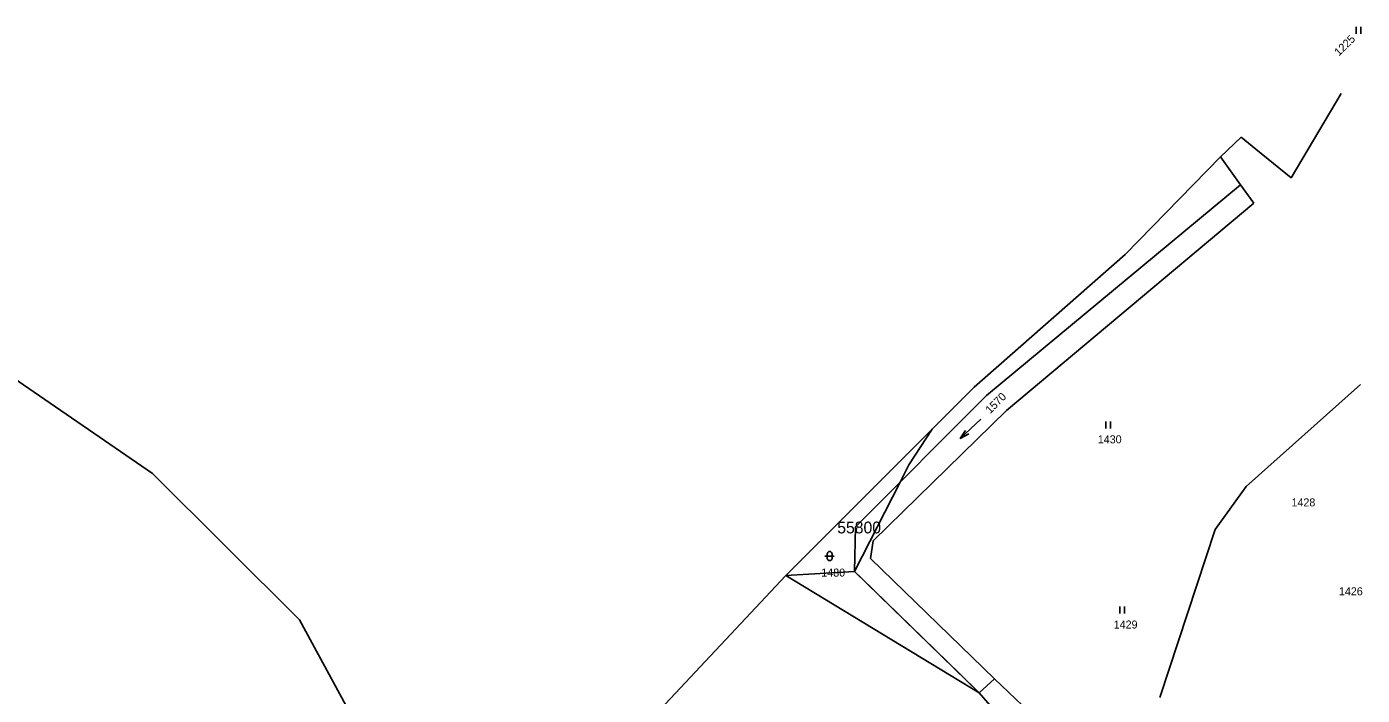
# Model space of a CAD drawing. Extents: x -792913 to -792113, y -1112764 to -1111548.
# Drawn here: x -792564 to -792280.2, y -1111690.4 to -1111548.5 of the extents above; entities that cross this region are included whole.
import ezdxf

# ---------------------------------------------------------------- set-up
doc = ezdxf.new("R2010")
doc.units = 0
for name, color, linetype in [('Vrstva 1', 7, 'Continuous'), ('Vrstva 11', 7, 'Continuous'), ('Vrstva 2', 7, 'Continuous'), ('Vrstva 3', 7, 'Continuous')]:
    doc.layers.add(name, color=color, linetype=linetype)

msp = doc.modelspace()

# ---------------------------------------------------------------- linework, layer by layer
at = {"layer": 'Vrstva 1'}
for p, q in [((-792284.7, -1111562.64), (-792295.38, -1111580.58)), ((-792306, -1111571.97), (-792310.36, -1111576.12)), ((-792306, -1111571.97), (-792306, -1111571.97)), ((-792302.87, -1111574.51), (-792306, -1111571.97)), ((-792330.62, -1111596.83), (-792310.36, -1111576.12)), ((-792310.36, -1111576.12), (-792306.1, -1111582.06)), ((-792302.87, -1111574.51), (-792302.87, -1111574.51)), ((-792295.38, -1111580.58), (-792302.87, -1111574.51)), ((-792306.1, -1111582.06), (-792360.09, -1111626.82)), ((-792306.1, -1111582.06), (-792303.31, -1111585.96)), ((-792295.38, -1111580.58), (-792295.38, -1111580.58)), ((-792303.31, -1111585.96), (-792355.85, -1111629.99)), ((-792303.31, -1111585.96), (-792303.31, -1111585.96)), ((-792362.73, -1111625), (-792330.62, -1111596.83)), ((-792537.29, -1111643.34), (-792573.5, -1111618.48)), ((-792402.71, -1111664.98), (-792362.73, -1111625)), ((-792304.88, -1111646.11), (-792280.6, -1111624.45)), ((-792360.09, -1111626.82), (-792387.93, -1111654.66)), ((-792355.85, -1111629.99), (-792384.15, -1111657.66)), ((-792506.06, -1111674.4), (-792537.29, -1111643.34)), ((-792311.52, -1111655.25), (-792304.88, -1111646.11)), ((-792387.93, -1111654.66), (-792388.1, -1111664.15)), ((-792323.22, -1111690.93), (-792311.52, -1111655.25)), ((-792384.15, -1111657.66), (-792384.7, -1111661.39)), ((-792384.7, -1111661.39), (-792358.41, -1111686.91)), ((-792402.71, -1111664.98), (-792456.34, -1111722.07)), ((-792361.64, -1111689.93), (-792402.71, -1111664.98)), ((-792388.1, -1111664.15), (-792361.64, -1111689.93)), ((-792485.77, -1111711.57), (-792506.06, -1111674.4)), ((-792358.41, -1111686.91), (-792361.64, -1111689.93)), ((-792358.41, -1111686.91), (-792358.41, -1111686.91)), ((-792358.41, -1111686.91), (-792339.22, -1111705.06)), ((-792344.27, -1111709.86), (-792361.64, -1111689.93))]:
    msp.add_line(p, q, dxfattribs=at)
at = {"layer": 'Vrstva 11'}
for p, q in [((-792310.36, -1111576.12), (-792306, -1111571.97)), ((-792330.62, -1111596.83), (-792310.36, -1111576.12)), ((-792362.73, -1111625), (-792330.62, -1111596.83)), ((-792371.64, -1111633.91), (-792362.73, -1111625)), ((-792402.71, -1111664.98), (-792371.64, -1111633.91)), ((-792371.64, -1111633.91), (-792376.56, -1111641.5)), ((-792376.56, -1111641.5), (-792378.42, -1111645.15)), ((-792378.42, -1111645.15), (-792388.1, -1111664.15)), ((-792402.71, -1111664.98), (-792388.1, -1111664.15)), ((-792388.1, -1111664.15), (-792386.54, -1111665.67)), ((-792386.54, -1111665.67), (-792365.76, -1111685.91)), ((-792365.76, -1111685.91), (-792361.64, -1111689.93)), ((-792361.64, -1111689.93), (-792344.27, -1111709.86))]:
    msp.add_line(p, q, dxfattribs=at)
at = {"layer": 'Vrstva 3'}
for p, q in [((-792281.52, -1111548.49), (-792281.52, -1111549.99)), ((-792280.52, -1111549.99), (-792280.52, -1111548.49)), ((-792361.272, -1111631.829), (-792365.668, -1111635.911)), ((-792334.76, -1111632.3), (-792334.76, -1111633.8)), ((-792333.76, -1111633.8), (-792333.76, -1111632.3)), ((-792331.73, -1111671.56), (-792331.73, -1111673.06)), ((-792330.73, -1111673.06), (-792330.73, -1111671.56))]:
    msp.add_line(p, q, dxfattribs=at)
for points in [[(-792363.863, -1111634.917), (-792365.668, -1111635.911), (-792364.543, -1111634.184)], [(-792394.41, -1111660.88), (-792393.14, -1111660.88), (-792392.41, -1111660.88)]]:
    msp.add_lwpolyline(points, dxfattribs=at)
msp.add_lwpolyline([(-792393.91, -1111660.38), (-792393.81, -1111660.09), (-792393.56, -1111659.91), (-792393.25, -1111659.91), (-792393, -1111660.09), (-792392.9, -1111660.38), (-792392.9, -1111661.38), (-792393, -1111661.67), (-792393.25, -1111661.85), (-792393.56, -1111661.85), (-792393.81, -1111661.67), (-792393.91, -1111661.38)], close=True, dxfattribs=at)

# ---------------------------------------------------------------- texts
at = {"layer": 'Vrstva 11'}
msp.add_text('55800', height=2.5, dxfattribs=at).set_placement((-792391.789, -1111656.06))
at = {"layer": 'Vrstva 2'}
for s, rotation, p in [('1225', 44.57612, (-792285.19, -1111554.814)), ('1570', 45.37826, (-792359.284, -1111630.78))]:
    msp.add_text(s, height=1.7, rotation=rotation, dxfattribs=at).set_placement(p)
for s, p in [('1430', (-792336.427, -1111636.94)), ('1428', (-792295.277, -1111650.33)), ('1480', (-792395.177, -1111665.23)), ('1426', (-792285.197, -1111669.21)), ('1429', (-792333.047, -1111676.26))]:
    msp.add_text(s, height=1.7, dxfattribs=at).set_placement(p)

doc.saveas('drawing.dxf')
